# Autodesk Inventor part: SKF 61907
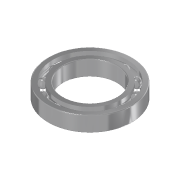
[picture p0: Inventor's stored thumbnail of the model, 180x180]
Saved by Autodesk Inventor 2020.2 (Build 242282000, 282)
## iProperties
+MSCProtocol1+ProtocolID: P00060228140304281
+MSCProtocol2+Protocol: P00060228140304281<@PID>[Version]<@EL>Version=2.2<@EL>[Files]<@EL>DataFile=SpiData|n024630a<@EL>[Synchronize]<@EL>ChangedVars=<@EL>[Calc]<@EL>DDmin=<@EL>DDmax=<
Manager: www.cadconsulting.pl
Company: Fabian Stasiak CAD Consulting
Shininess: 20.0
Length Units: 11269
Angle Units: 11279
Time Units: 11290
Mass Units: 11283
Length Display Precision: 3
Angle Display Precision: 2
Created: 2001-01
Part Number: SKF 61907
Material: Stal
Document SubType Name: Modeling
Description: Łożysko SKF 61907
Stock Number: SKF 61907
Project: Przekładnia X51
Designer: F.Stasiak
Density: 7.85 g/cm^3
Appearance: Chrom
Density: 7.86
Volumn: 47.63899704516156
Area: 199.2492810037185
PropertySet Name: Model Information
Control State: 0
Master: False
Checked Out: False
BOM1: Łożysko
BOM2: SKF 61907
Author: F.Stasiak
Subject: Zbiór ćwiczeń. Autodesk Inventor 2020. Kurs podstawowy
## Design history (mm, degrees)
node "Sketch1"
node "WorkPoint1"
sketch "Sketch2"
  geometry: L1 (17.5, 10)-(27.5, 10); L2 (17.5, 0)-(17.5, 10); L3 (27.5, 0)-(17.5, 0); L4 (27.5, 10)-(27.5, 0); L5 (0, 0)-(0, 20); L6 (0, 0)-(0, 20); L7 (-3.6, 0)-(46.8, 0) reference
  constraints: 12 end point, 3 vertical, 2 horizontal, 1 collinear, 1 other
  dimensions: "d1" = 35 diameter of L1.start L5 (= prf_d); "d3" = 55 diameter of L1.end L5 (= prf_dd); "d5" = 10 distance of L2.start L1.start (= msp_mdtd2)
revolve "RevolutionFull1" sketch "Sketch2" stored, may be unused: angle "d6" = 360 deg
node "WorkAxis1"
node "WorkPlane3"
sketch "Sketch3"
  geometry: L1 (24.3, 10)-(24.3, 7.4); L2 (20.7, 10)-(24.3, 10); L3 (20.7, 7.4)-(20.7, 10); L4 (20.7, 0)-(20.7, 2.6); L5 (24.3, 0)-(20.7, 0); L6 (24.3, 2.6)-(24.3, 0); L7 (27.5, 0)-(-27.5, 0) reference; L8 (27.5, 10)-(-27.5, 10) reference; L9 (0, -42.29)-(0, 61.29); L10 (0, 92.365)-(0, -52.649) reference; A1 r 3 centre (22.5, 5) between (24.3, 2.6) and (24.3, 7.4); A2 r 3 centre (22.5, 5) between (20.7, 7.4) and (20.7, 2.6)
  constraints: 14 end point, 4 collinear, 4 point on circle, 4 vertical, 2 centre point, 2 concentric, 2 horizontal, 2 point on line
  dimensions: "d9" = 6 diameter of A1 (= msp_mdtd6); "d21" = 20.7 distance between parallel lines of L9 L4 (= 0.5 x msp_d1); "d22" = 22.5 distance from line of L9 A1.centre (= 0.5 x msp_ds); "d23" = 24.3 distance between parallel lines of L9 L6 (= 0.5 x msp_dd1)
revolve "RevolutionFull2" sketch "Sketch3" stored, may be unused: angle "d10" = 360 deg
node "WorkPlane4"
node "Sketch4"
node "WorkPoint2"
revolve "RevolutionFull3" stored, may be unused: angle "d16" = 360 deg
pattern_circular "PolarAray1" dims "d17" = 116.5 (= msp_pocet), angle "d19" = 360 deg
fillet "Fillet1" dims "d20" = 0.6 (= prf_r)
node "Bryła1"
node "Korpusy bryłowe"
node "Korpusy powierzchniowe"
sketch "Sketch5"
  geometry: L1 (22.5, 2)-(22.5, 8); L2 (24.3, 0)-(-24.3, 0) reference; L3 (22.5, 2)-(22.5, 8); A1 r 3 centre (22.5, 5) between (22.5, 2) and (22.5, 8); A2 r 3 centre (22.5, 5) between (24.3, 2.6) and (24.3, 7.4) reference
  constraints: 4 end point, 2 point on circle, 1 centre point, 1 concentric, 1 vertical
  dimensions: "d13" = 0 horizontal distance of A1.centre L1.start; "d15" = 6.0001 diameter of A1 (computed from msp_mdtd6)
other parameters: "prf_d" = 35 [user parameter; used in 3 equation terms], "prf_dd" = 55 [user parameter; used in 3 equation terms], "prf_r" = 0.6 [user parameter; used in 1 equation term], "msp_ds" = 45 (= 0.5 x prf_d + 0.5 x prf_dd) [user parameter; used in 5 equation terms], "msp_d0" = 6 (= -0.3 x prf_d + 0.3 x prf_dd) [user parameter; used in 4 equation terms], "msp_d1" = 41.4 (= msp_ds - 0.6 x msp_d0) [user parameter; used in 1 equation term], "msp_dd1" = 48.6 (= msp_ds + 0.6 x msp_d0) [user parameter; used in 1 equation term], "msp_pom" = 67.5 (= 1.5 x msp_ds) [user parameter; used in 1 equation term], "msp_mdtd2" = 10 (= prf_b) [user parameter; used in 3 equation terms], "msp_mdtd4" = 45 (= msp_ds) [user parameter], "msp_mdtd6" = 6 (= msp_d0) [user parameter; used in 2 equation terms], "msp_mdtd7" = 5 (= 0.5 x msp_mdtd2) [user parameter], "msp_pocet" = 116.5 (computed from msp_d0, msp_pom) [user parameter; used in 1 equation term], "d2" = 72 (derived), "d4" = 19 (derived), "d7" = 0, "d8" = 15.6 (derived), "d12" = 0 (derived), "d14" = 15.6001 (derived), "d25" = 0
